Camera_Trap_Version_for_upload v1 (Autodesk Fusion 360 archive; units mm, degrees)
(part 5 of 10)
sketch "Sketch25" plane through (105, 0, 0) normal (-1, 0, 0) x axis (0, -1, 0)
  line L1 (-34.2232, 143.2913) -> (-36.1659, 143.2913)
  line L2 (-34.2, 143.2798) -> (-34.2232, 143.2913)
  line L3 (-36.1659, 143.2798) -> (-34.2, 143.2798)
  line L4 (-36.1659, 143.2913) -> (-36.1659, 143.2798)
  line L5 (-36.1659, 139.8364) -> (-36.1659, 139.8248)
  line L6 (-34.2, 139.8364) -> (-36.1659, 139.8364)
  line L7 (-34.2232, 139.8248) -> (-34.2, 139.8364)
  line L8 (-36.1659, 139.8248) -> (-34.2232, 139.8248)
  line L9 (10, 119) -> (-33, 119)
  line L10 (18, 145) -> (18, 127)
  line L11 (-33, 153) -> (10, 153)
  line L12 (-41, 127) -> (-41, 145)
  line L13 (11.3693, 148.5581) -> (-24.3276, 148.5581)
  line L14 (11.3693, 123.5581) -> (-24.3276, 123.5581)
  line L15 (-33.7807, 138.4085) -> (-33.7807, 138.4081)
  line L16 (-33.7807, 138.4085) -> (-34.161, 138.0281)
  line L17 (-34.161, 145.088) -> (-33.7807, 144.7077)
  line L18 (-33.7807, 144.7081) -> (-33.7807, 144.7077)
  line L19 (-36.1659, 143.2798) -> (-36.1659, 143.2913)
  line L20 (-36.1659, 143.2913) -> (-34.2232, 143.2913)
  line L21 (-34.2, 143.2798) -> (-34.2232, 143.2913)
  line L22 (-36.661, 145.088) -> (-34.161, 145.088)
  curve K1 (-37.1562, 143.1166) -> (-37.1489, 143.0744)
  line L23 (-36.1659, 143.2798) -> (-34.2, 143.2798)
  line L24 (-36.1659, 139.8364) -> (-34.2, 139.8364)
  curve K2 (-37.1562, 144.5928) -> (-36.661, 145.088)
  line L25 (-37.1562, 143.1187) -> (-37.1562, 143.1166)
  line L26 (-36.1659, 139.8248) -> (-36.1659, 139.8364)
  line L27 (-36.1659, 139.8248) -> (-34.2232, 139.8248)
  line L28 (-34.2232, 139.8248) -> (-34.2, 139.8364)
  line L29 (-36.661, 138.0281) -> (-34.161, 138.0281)
  curve K3 (-37.1562, 143.0321) -> (-37.1489, 143.0744)
  curve K4 (-37.1489, 140.0417) -> (-37.1562, 140.084)
  line L30 (-24.3276, 123.5581) -> (-32.6307, 123.5581)
  line L31 (-24.3276, 148.5581) -> (-32.6307, 148.5581)
  line L32 (-33.6307, 147.5581) -> (-33.6307, 144.5581)
  line L33 (-33.6307, 133.5581) -> (-33.6307, 138.5581)
  line L34 (-33.6307, 127.5581) -> (-33.6307, 124.5581)
  line L35 (12.3693, 127.5581) -> (12.3693, 144.5581)
  line L36 (12.3693, 147.5581) -> (12.3693, 144.5581)
  line L37 (12.3693, 127.5581) -> (12.3693, 124.5581)
  line L38 (-37.1562, 139.9995) -> (-37.1562, 139.9974)
  curve K5 (-36.661, 138.0281) -> (-37.1562, 138.5233)
  line L39 (-33.7807, 127.5581) -> (-33.7807, 128.0581)
  line L40 (-33.7807, 133.0581) -> (-33.7807, 133.5581)
  line L41 (-36.6307, 128.0581) -> (-36.6307, 130.5581)
  line L42 (-36.6307, 130.5581) -> (-36.6307, 133.0581)
  line L43 (-33.7807, 144.7081) -> (-33.6307, 144.5581)
  line L44 (-33.7807, 138.4081) -> (-33.6307, 138.5581)
  line L45 (-37.1562, 143.1187) -> (-37.1562, 144.5928)
  line L46 (-37.1562, 140.084) -> (-37.1562, 143.0321)
  line L47 (-37.1562, 138.5233) -> (-37.1562, 139.9974)
  line L48 (-33.6307, 127.5581) -> (-33.7807, 127.5581)
  line L49 (-33.6307, 133.5581) -> (-33.7807, 133.5581)
  line L50 (-33.7807, 128.0581) -> (-36.6307, 128.0581)
  line L51 (-33.7807, 133.0581) -> (-36.6307, 133.0581)
  line L52 (-46.5669, 127) -> (-46.5669, 145)
  line L53 (10, 113.4331) -> (-33, 113.4331)
  line L54 (23.5669, 145) -> (23.5669, 127)
  line L55 (-33, 158.5669) -> (10, 158.5669)
  arc A1 centre (-33, 127) radius 8 clockwise from (-33, 119) to (-41, 127)
  arc A2 centre (10, 127) radius 8 clockwise from (18, 127) to (10, 119)
  arc A3 centre (10, 145) radius 8 clockwise from (10, 153) to (18, 145)
  arc A4 centre (-33, 145) radius 8 clockwise from (-41, 145) to (-33, 153)
  closed curve K6 centre (-36.6611, 139.9995)
  arc A5 centre (11.3693, 124.5581) radius 1 clockwise from (12.3693, 124.5581) to (11.3693, 123.5581)
  arc A6 centre (11.3693, 147.5581) radius 1 clockwise from (11.3693, 148.5581) to (12.3693, 147.5581)
  arc A7 centre (-32.6307, 147.5581) radius 1 clockwise from (-33.6307, 147.5581) to (-32.6307, 148.5581)
  arc A8 centre (-32.6307, 124.5581) radius 1 clockwise from (-32.6307, 123.5581) to (-33.6307, 124.5581)
  arc A9 centre (-33, 145) radius 13.5669 clockwise from (-46.5669, 145) to (-33, 158.5669)
  arc A10 centre (-33, 127) radius 13.5669 clockwise from (-33, 113.4331) to (-46.5669, 127)
  arc A11 centre (10, 127) radius 13.5669 clockwise from (23.5669, 127) to (10, 113.4331)
  arc A12 centre (10, 145) radius 13.5669 clockwise from (10, 158.5669) to (23.5669, 145)
  dimension "d1087" = 5.5669
extrude "Extrude51" add sketch "Sketch25" profile of A1 L9 A2 L10 A3 L11 A4 L12 A12 A9 A10 A11 L55 L53 L54 L52 against normal blind 20
extrude "Extrude4" cut sketch "Sketch25" profile of L1 L2 L3 L4 L5 L6 L7 L8 A1 L9 A2 L10 A3 L11 A4 L12 L13 L14 L15 L16 L17 L18 L19 L20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 blind -24 from offset -3
sketch "Sketch26" plane through (0, 46.5669, 0) normal (0, 1, 0) x axis (-1, 0, 0)
  line L1 (-105, 145) -> (-105, 127)
  line L2 (-125, 145) -> (-105, 145)
  line L3 (-125, 127) -> (-125, 145)
  line L4 (-105, 127) -> (-125, 127)
  line L5 (-113, 135) -> (-125, 135)
  line L6 (-113, 127) -> (-113, 135)
  line L7 (-125, 127) -> (-113, 127)
  line L8 (-125, 135) -> (-125, 127)
  point P6 (-125, 135)
  point P7 (-113, 135)
  horizontal L5
  vertical L6
  horizontal L7
  vertical L8
  dimension "d1096" distance P6 P7 = 12
extrude "Extrude53" cut sketch "Sketch26" profile of L3 L4 L5 L6 L7 L8 against normal blind 10
sketch "Sketch27" plane through (132, 0, 0) normal (1, 0, 0) x axis (0, 1, 0)
  line L1 (-10, 119) -> (33, 119)
  line L2 (-18, 145) -> (-18, 127)
  line L3 (33, 153) -> (-10, 153)
  line L4 (41, 127) -> (41, 145)
  line L5 (53, 254.9308) -> (53, 30)
  line L6 (2.6295, 254.9308) -> (53, 254.9308)
  line L7 (-35.395, 253.2053) -> (-2.6295, 254.9308)
  curve K1 (-35.395, 253.2053) -> (-39.3474, 235.851)
  line L8 (33, 30) -> (2.8201, 30)
  line L9 (53, 30) -> (33, 30)
  line L10 (41, 136) -> (-18, 136)
  line L11 (11, 153) -> (11.5, 119)
  arc A1 centre (33, 127) radius 8 clockwise from (41, 127) to (33, 119)
  arc A2 centre (-10, 127) radius 8 clockwise from (-10, 119) to (-18, 127)
  arc A3 centre (-10, 145) radius 8 clockwise from (-18, 145) to (-10, 153)
  arc A4 centre (33, 145) radius 8 clockwise from (33, 153) to (41, 145)
  arc A5 centre (0, 205) radius 50 clockwise from (-2.6295, 254.9308) to (2.6295, 254.9308)
  arc A6 centre (0, 205) radius 50 clockwise from (-40.632, 175.8617) to (-39.3474, 235.851)
  arc A7 centre (-81.264, 146.7234) radius 50 clockwise from (-40.632, 175.8617) to (-31.815, 139.3208)
  arc A8 centre (-1.7685, 134.8228) radius 30.3814 clockwise from (-32.1399, 134.0465) to (-31.815, 139.3208)
  arc A9 centre (-82.1236, 132.769) radius 50 clockwise from (-32.1399, 134.0465) to (-39.6517, 106.3845)
  arc A10 centre (2.8201, 80) radius 50 clockwise from (2.8201, 30) to (-39.6517, 106.3845)
  circle C1 centre (-17.953, 152.353) radius 1.4
  circle C2 centre (39.9595, 153.2046) radius 1.4
  circle C3 centre (39.9595, 118.7954) radius 1.4
  circle C4 centre (-16.9412, 117.9586) radius 1.4
  point P32 (-18, 136)
  point P33 (41, 136)
  point P34 (11.5, 119)
  point P35 (11, 153)
  midpoint L2 P32
  midpoint L4 P33
  midpoint L1 P34
  coincident L3 P35
  symmetric C1 L11 C2
  symmetric L10 C2 C3
  symmetric L11 C3 C4
  dimension "d1099" diameter C1 = 2.8
extrude "Extrude54" cut sketch "Sketch27" profile of C1 C2 C3 C4 against normal blind 5
combine "Combine1" bodies "Right_wall (2)"
combine "Combine2"
sketch "Sketch3" plane through (136, 0, 0) normal (1, 0, 0) x axis (0, 1, 0)
  circle C1 centre (0, 70.6) radius 4.1
  circle C2 centre (0, 70.6) radius 25
  concentric C1 C2
  dimension "d1102" diameter C2 = 50
extrude "Extrude7" new body sketch "Sketch3" distance 10 bodies "wrong_cutting_tool"
thread "Thread1" ThreadOffset 0 ThreadLength 10
combine "Combine6" bodies "Right_wall (2) (1)"
extrude "Extrude55" cut of existing geometry blind -10
extrude "Extrude10" new body sketch "Sketch1" profile of C1 C2 C3 L1 L2 L3 L4 A1 A2 A3 A4 L7 C4 C5 C6 C7 C8 C9 C10 C11 along normal blind 8
combine "Combine7" bodies "Right_wall_Final"
extrude "Extrude5" cut of existing geometry blind -20
combine "Combine8"
extrude "Extrude11" cut of existing geometry blind -10
extrude "Extrude12" cut of existing geometry blind -15
extrude "Extrude13" cut of existing geometry blind -15
extrude "Extrude14" cut of existing geometry blind -15
extrude "Extrude61" new body sketch "Small_bearings_R" profile of C4 C5 C6 C7 C8 C9 C13 C14 against normal blind 12 bodies "Cut_tool"
extrude "Extrude62" new body sketch "Small_bearings_R" profile of C1 C2 C3 C10 C11 C12 C15 C16 against normal blind 12 bodies "Cut_tool (1)"
thread "Thread1" ThreadOffset 0 ThreadLength 10
thread "Thread2" ThreadOffset 0 ThreadLength 10
combine "Combine9"
extrude "Extrude63" new body sketch "Small_bearings_L" profile of C1 C2 C4 C5 C7 C8 along normal blind 4
extrude "Extrude64" add of existing geometry blind 4
extrude "Extrude65" cut of existing geometry blind -4
sketch "Sketch8" plane through (0, 0, 0) normal (1, 0, 0) x axis (0, 1, 0)
sketch "Sketch9" plane through (135.8025, 0, 0) normal (1, 0, 0) x axis (0, 1, 0)
  line L1 (52.3693, 253.4503) -> (59.3693, 253.4503)
  line L2 (52.3693, 30.245) -> (52.3693, 253.4503)
  line L3 (59.3693, 30.245) -> (52.3693, 30.245)
  line L4 (59.3693, 253.4503) -> (59.3693, 30.245)
  line L5 (64.8196, 255.1758) -> (59.3693, 249.9246)
  line L6 (64.8196, 265) -> (64.8196, 255.1758)
  line L7 (59.3693, 265) -> (64.8196, 265)
  line L8 (59.3693, 265) -> (59.3693, 253.4503)
  point P6 (59.3693, 249.9246)
  point P2 (59.3693, 253.4503)
  point P9 (59.3693, 253.4503)
  coincident L4 P6
  vertical L6
  perpendicular L6 L7
  coincident P2 P9
  perpendicular L7 L8
sweep "Sweep1" sketch "Sketch9" TwistAngle 0 TaperAngle 0
combine "Combine1" bodies "BackWall"
combine "Combine1" sketch "Tests" bodies "Right_wall_Final"
combine "Combine1" bodies "Right_wall_Final"
combine "Combine1" bodies "Right_wall_Final"
combine "Combine1" sketch "Tests" bodies "Print_Test"
combine "Combine1" bodies "interior_motor_holder"
component_from_bodies "Body->Comp1"
offset_faces "OffsetFaces1" distance -1
offset_faces "OffsetFaces2" distance -1
offset_faces "OffsetFaces1" distance 1
offset_faces "OffsetFaces2" distance 1
sketch "Sketch1" plane through (0, 35, 0) normal (0, -1, 0) x axis (1, 0, 0)
  line L1 (61.25, 114.9665) -> (61.25, 151.0335)
  line L2 (51.25, 114.9665) -> (61.25, 114.9665)
  line L3 (51.25, 151.0335) -> (51.25, 114.9665)
  line L4 (61.25, 151.0335) -> (51.25, 151.0335)
  line L5 (-7.775, 205) -> (-7.775, 207.6585)
  line L6 (-21, 205) -> (-7.775, 205)
  line L7 (-21, 195.1585) -> (-21, 205)
  line L8 (-7.775, 195.1585) -> (-21, 195.1585)
  line L9 (-7.775, 175.1585) -> (-7.775, 195.1585)
  line L10 (33.225, 170.1585) -> (-2.775, 170.1585)
  line L11 (43.225, 110.9415) -> (43.225, 160.1585)
  line L12 (64.275, 105.9415) -> (48.225, 105.9415)
  line L13 (69.275, 175.1585) -> (69.275, 110.9415)
  line L14 (12.225, 180.1585) -> (64.275, 180.1585)
  line L15 (2.225, 208.1585) -> (2.225, 190.1585)
  line L16 (-5.275, 210.1585) -> (0.225, 210.1585)
  line L17 (48.7344, 135.5025) -> (48.7344, 145.5025)
  line L18 (45.7344, 145.5025) -> (45.7344, 135.5025)
  line L19 (66.7656, 135.5025) -> (66.7656, 145.5025)
  line L20 (63.7656, 145.5025) -> (63.7656, 135.5025)
  line L21 (65.2656, 146.5025) -> (65.2656, 145.5025)
  line L22 (63.7656, 146.5025) -> (63.7656, 145.5025)
  line L23 (66.7656, 146.5025) -> (66.7656, 145.5025)
  line L24 (65.5, 140.5025) -> (66.7656, 140.5025)
  line L25 (65.5, 140.5025) -> (66.7656, 140.5025)
  line L26 (66.7656, 134.5025) -> (66.7656, 135.5025)
  line L27 (63.7656, 134.5025) -> (63.7656, 135.5025)
  line L28 (56.25, 147) -> (56.25, 151.0335)
  line L29 (45.7344, 146.5025) -> (45.7344, 145.5025)
  line L30 (48.7344, 146.5025) -> (48.7344, 145.5025)
  line L31 (48.7344, 145.5025) -> (48.7344, 135.5025)
  line L32 (45.7344, 135.5025) -> (45.7344, 145.5025)
  line L33 (45.7344, 134.5025) -> (45.7344, 135.5025)
  line L34 (48.7344, 134.5025) -> (48.7344, 135.5025)
  line L35 (43.225, 119.0366) -> (3.126, 170.1585)
  line L36 (43.225, 132.2223) -> (13.4686, 170.1585)
  arc A1 centre (-5.275, 207.6585) radius 2.5 clockwise from (-7.775, 207.6585) to (-5.275, 210.1585)
  arc A2 centre (-2.775, 175.1585) radius 5 clockwise from (-2.775, 170.1585) to (-7.775, 175.1585)
  arc A3 centre (33.225, 160.1585) radius 10 clockwise from (33.225, 170.1585) to (43.225, 160.1585)
  arc A4 centre (48.225, 110.9415) radius 5 clockwise from (48.225, 105.9415) to (43.225, 110.9415)
  arc A5 centre (64.275, 110.9415) radius 5 clockwise from (69.275, 110.9415) to (64.275, 105.9415)
  arc A6 centre (64.275, 175.1585) radius 5 clockwise from (64.275, 180.1585) to (69.275, 175.1585)
  arc A7 centre (12.225, 190.1585) radius 10 clockwise from (12.225, 180.1585) to (2.225, 190.1585)
  arc A8 centre (0.225, 208.1585) radius 2 clockwise from (0.225, 210.1585) to (2.225, 208.1585)
  arc A9 centre (47.2344, 135.5025) radius 1.5 clockwise from (48.7344, 135.5025) to (45.7344, 135.5025)
  arc A10 centre (47.2344, 145.5025) radius 1.5 clockwise from (45.7344, 145.5025) to (48.7344, 145.5025)
  arc A11 centre (65.2656, 135.5025) radius 1.5 clockwise from (66.7656, 135.5025) to (63.7656, 135.5025)
  arc A12 centre (65.2656, 145.5025) radius 1.5 clockwise from (63.7656, 145.5025) to (66.7656, 145.5025)
  circle C1 centre (65.2656, 145.5025) radius 1.5
  circle C2 centre (65.2656, 146.5025) radius 1.5
  circle C3 centre (65.2656, 134.5025) radius 1.5
  circle C4 centre (47.2344, 146.5025) radius 1.5
  circle C5 centre (47.2344, 134.5025) radius 1.5
  point P40 (66.7656, 145.5025)
  point P46 (65.2656, 145.5025)
  point P47 (65.2656, 145.5025)
  point P48 (65.2656, 146.5025)
  point P49 (65.2656, 146.5025)
  point P44 (63.7656, 145.5025)
  point P50 (63.7656, 145.5025)
  point P51 (63.7656, 146.5025)
  point P52 (66.7656, 145.5025)
  point P53 (66.7656, 146.5025)
  point P54 (66.7656, 140.5025)
  point P61 (63.7656, 135.5025)
  point P62 (63.7656, 134.5025)
  point P59 (66.7656, 135.5025)
  point P60 (66.7656, 134.5025)
  point P56 (66.7656, 140.5025)
  point P55 (65.5, 140.5025)
  point P57 (65.5, 140.5025)
  point P63 (56.25, 151.0335)
  point P72 (45.7344, 145.5025)
  point P41 (66.7656, 135.5025)
  point P73 (45.7344, 135.5025)
  point P42 (63.7656, 135.5025)
  point P70 (48.7344, 135.5025)
  point P71 (48.7344, 145.5025)
  point P68 (48.7344, 145.5025)
  point P69 (48.7344, 146.5025)
  point P66 (45.7344, 145.5025)
  point P67 (45.7344, 146.5025)
  point P74 (45.7344, 135.5025)
  point P75 (45.7344, 134.5025)
  point P76 (48.7344, 135.5025)
  point P77 (48.7344, 134.5025)
  point P79 (3.126, 170.1585)
  point P80 (43.225, 119.0366)
  point P81 (13.4686, 170.1585)
  point P82 (43.225, 132.2223)
  concentric A12 C1
  coincident P40 C1
  coincident P46 P47
  vertical L21
  coincident P48 P49
  coincident P44 P50
  coincident C2 P51
  tangent C2 L22
  coincident P40 P52
  coincident C2 P53
  tangent C2 L23
  midpoint L19 P54
  perpendicular L19 L24
  symmetric C2 L24 C3
  symmetric P50 L24 P61
  symmetric P51 L24 P62
  symmetric P52 L24 P59
  symmetric P53 L24 P60
  symmetric P54 L24 P56
  symmetric P55 L24 P57
  midpoint L4 P63
  perpendicular L4 L28
  symmetric P40 L28 P72
  symmetric P41 L28 P73
  symmetric P42 L28 P70
  symmetric P44 L28 P71
  symmetric C2 L28 C4
  symmetric P50 L28 P68
  symmetric P51 L28 P69
  symmetric P52 L28 P66
  symmetric P53 L28 P67
  symmetric C3 L28 C5
  symmetric P59 L28 P74
  symmetric P60 L28 P75
  symmetric P61 L28 P76
  symmetric P62 L28 P77
  coincident L10 P79
  coincident L11 P80
  coincident L10 P81
  coincident L11 P82
  parallel L35 L36
  dimension "d1241" distance P47 P48 = 1
  dimension "d1242" diameter C2 = 3
extrude "Extrude1" cut sketch "Sketch1" profile of A9 A10 A11 A12 C1 C2 L22 L23 C3 L26 L27 C4 L29 L30 L33 L34 C5 to an object
offset_faces "OffsetFaces3" distance -0.1
offset_faces "OffsetFaces4" distance -0.1
offset_faces "OffsetFaces5" distance -0.1
offset_faces "OffsetFaces6" distance -0.1
extrude "Extrude2" add sketch "Sketch1" profile of L10 L11 L35 L36 against normal blind 6
offset_faces "OffsetFaces7" distance -1
scale "Scale1" ScaleFactor 0.97
copy_paste_bodies "CopyPasteBodies3"
base_feature "Base Feature1" bodies "Right_Wall_Cap_Low (1)", "Handle_Exterior"
sketch "Sketch1" plane through (0, 0, 0) normal (0, 1, 0) x axis (1, 0, 0)
  line L1 (129, -220.4) -> (129, -190.4)
  line L2 (129, -190.4) -> (129, -180.4)
  line L3 (129, -180.4) -> (136, -180.4)
  line L4 (129, -230.4) -> (136, -230.4)
  line L5 (129, -230.4) -> (129, -220.4)
  line L6 (136, -230.4) -> (136, -235.4)
  line L7 (136, -175.4) -> (136, -180.4)
  line L8 (139, -235.4) -> (136, -235.4)
  line L9 (139, -175.4) -> (136, -175.4)
  line L10 (139, -175.4) -> (139, -190.4)
  line L11 (139, -190.4) -> (139, -220.4)
  line L12 (139, -220.4) -> (139, -235.4)
  line L13 (158, -168.5) -> (158, -196)
  line L14 (158, -196) -> (158, -223.5)
  line L15 (138, -168.5) -> (138, -182.9)
  line L16 (138, -209.1) -> (138, -223.5)
  line L17 (129, -182.9) -> (129, -196)
  line L18 (129, -196) -> (129, -209.1)
  line L19 (158, -223.5) -> (138, -223.5)
  line L20 (158, -168.5) -> (138, -168.5)
  line L21 (138, -209.1) -> (129, -209.1)
  line L22 (138, -182.9) -> (129, -182.9)
extrude "Extrude2" new body of existing geometry blind 9 named "d703_1" bodies "Coil"
thread "Thread1" ThreadOffset 0 named "d705_1" ThreadLength 10 named "d706_1"
fillet "Fillet1" radius 5 named "d708_1"
scale "Scale1" ScaleFactor 0.97 named "d1151_1"
combine "Combine1" bodies "Right_wall_Final"
sketch "Sketch6" plane through (135.8025, 0, 0) normal (1, 0, 0) x axis (0, 1, 0)
  curve K1 (-42.0969, 92.8551) -> (-42.4569, 81.9281)
  curve K2 (-35.7603, 81.9281) -> (-36.1203, 92.8551)
  curve K3 (-42.0969, 202.8551) -> (-42.4569, 191.9281)
  curve K4 (-35.7603, 191.9281) -> (-36.1203, 202.8551)
  line L1 (1.9988, 255.1758) -> (52.3693, 255.1758)
  line L2 (-36.0257, 253.4503) -> (-3.2602, 255.1758)
  curve K5 (-36.0257, 253.4503) -> (-39.9781, 236.096)
  line L3 (32.3693, 30.245) -> (2.1894, 30.245)
  line L4 (52.3693, 30.245) -> (32.3693, 30.245)
  line L5 (59.3693, 30.245) -> (52.3693, 30.245)
  line L6 (59.3693, 249.9246) -> (59.3693, 30.245)
  line L7 (64.8196, 255.1758) -> (59.3693, 249.9246)
  line L8 (64.8196, 265) -> (64.8196, 255.1758)
  line L9 (59.3693, 265) -> (64.8196, 265)
  line L10 (59.3693, 253.4503) -> (59.3693, 265)
  line L11 (-10.6307, 119.245) -> (32.3693, 119.245)
  line L12 (-18.6307, 145.245) -> (-18.6307, 127.245)
  line L13 (32.3693, 153.245) -> (-10.6307, 153.245)
  line L14 (40.3693, 127.245) -> (40.3693, 145.245)
  curve K6 (3.3853, 45.9804) -> (18.082, 84.0954)
  curve K7 (-6.8655, 92.093) -> (-17.0683, 52.5374)
  line L15 (-25, 220.4) -> (-25, 190.4)
  line L16 (15, 230.4) -> (-15, 230.4)
  line L17 (25, 190.4) -> (25, 220.4)
  line L18 (-15, 180.4) -> (15, 180.4)
  line L19 (-60.3135, 107.7788) -> (-50, 270)
  line L20 (33.9876, 93.3188) -> (-60.3135, 107.7788)
  line L21 (20.222, 41.7577) -> (33.9876, 93.3188)
  line L22 (-41.5097, 45.9804) -> (20.222, 41.7577)
  line L23 (-12.1668, 16.3902) -> (-41.5097, 45.9804)
  line L24 (70, 20) -> (-12.1668, 16.3902)
  line L25 (70, 273.158) -> (70, 20)
  line L26 (-50, 270) -> (70, 273.158)
  line L27 (-41.5097, 45.9804) -> (-47.6821, 105.8419)
  line L28 (52.3693, 255.1758) -> (52.3693, 253.4503)
  line L29 (52.3693, 253.4503) -> (59.3693, 253.4503)
  arc A1 centre (-39.1086, 86.6236) radius 6.911 clockwise from (-42.0969, 92.8551) to (-36.1203, 92.8551)
  arc A2 centre (-39.1086, 86.6236) radius 5.767 clockwise from (-35.7603, 81.9281) to (-42.4569, 81.9281)
  arc A3 centre (-39.1086, 196.6236) radius 6.911 clockwise from (-42.0969, 202.8551) to (-36.1203, 202.8551)
  arc A4 centre (-39.1086, 196.6236) radius 5.767 clockwise from (-35.7603, 191.9281) to (-42.4569, 191.9281)
  circle C1 centre (27.5, 205.4) radius 1.65
  circle C2 centre (0, 177.9) radius 1.65
  circle C3 centre (-27.5, 205.4) radius 1.65
  circle C4 centre (0, 232.9) radius 1.65
  arc A5 centre (-0.6307, 205.245) radius 50 clockwise from (-3.2602, 255.1758) to (1.9988, 255.1758)
  arc A6 centre (-0.6307, 205.245) radius 50 clockwise from (-41.2627, 176.1067) to (-39.9781, 236.096)
  arc A7 centre (-81.8947, 146.9684) radius 50 clockwise from (-41.2627, 176.1067) to (-32.4457, 139.5658)
  arc A8 centre (-2.3992, 135.0677) radius 30.3814 clockwise from (-32.7706, 134.2915) to (-32.4457, 139.5658)
  arc A9 centre (-82.7543, 133.0139) radius 50 clockwise from (-32.7706, 134.2915) to (-40.2825, 106.6295)
  arc A10 centre (2.1894, 80.245) radius 50 clockwise from (2.1894, 30.245) to (-40.2825, 106.6295)
  arc A11 centre (32.3693, 127.245) radius 8 clockwise from (40.3693, 127.245) to (32.3693, 119.245)
  arc A12 centre (-10.6307, 127.245) radius 8 clockwise from (-10.6307, 119.245) to (-18.6307, 127.245)
  arc A13 centre (-10.6307, 145.245) radius 8 clockwise from (-18.6307, 145.245) to (-10.6307, 153.245)
  arc A14 centre (32.3693, 145.245) radius 8 clockwise from (32.3693, 153.245) to (40.3693, 145.245)
  circle C5 centre (39.3288, 119.0404) radius 1.4
  circle C6 centre (39.3288, 153.4496) radius 1.4
  circle C7 centre (-17.5719, 118.2036) radius 1.4
  circle C8 centre (-18.5837, 152.598) radius 1.4
  arc A15 centre (0, 70.6) radius 24.8513 clockwise from (3.3853, 45.9804) to (-17.0683, 52.5374)
  arc A16 centre (0, 70.6) radius 22.5629 clockwise from (-6.8655, 92.093) to (18.082, 84.0954)
  arc A17 centre (-15, 220.4) radius 10 clockwise from (-25, 220.4) to (-15, 230.4)
  arc A18 centre (15, 220.4) radius 10 clockwise from (15, 230.4) to (25, 220.4)
  arc A19 centre (15, 190.4) radius 10 clockwise from (25, 190.4) to (15, 180.4)
  arc A20 centre (-15, 190.4) radius 10 clockwise from (-15, 180.4) to (-25, 190.4)
  point P79 (-47.6821, 105.8419)
  parallel L8 L25
  coincident L20 P79
extrude "Extrude1" cut sketch "Sketch6" profile of K3 A3 K4 A4 C1 C2 C3 C4 L1 A5 L2 K5 A6 A7 A8 A9 A10 L3 L4 L5 L6 L7 L8 L9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 against normal blind 240 bodies "Right_wall_Final (1)"
combine "Combine1"
offset_faces "OffsetFaces1" distance 7
position "Position29"
sketch "Sketch28" plane through (-24, 0, 0) normal (-1, 0, 0) x axis (0, -1, 0)
  line L1 (-46.1387, 104.755) -> (-18.6307, 104.755)
  line L2 (-49.1387, 175.7967) -> (-49.1387, 107.755)
  line L3 (-18.6307, 178.7967) -> (-46.1387, 178.7967)
  line L4 (-15.6307, 107.755) -> (-15.6307, 175.7967)
  line L5 (-35, 194) -> (-35, 213)
  line L6 (-42, 194) -> (-35, 194)
  line L7 (-42, 213) -> (-42, 194)
  line L8 (-35, 213) -> (-42, 213)
  line L9 (-53, 30) -> (-53, 254.9308)
  line L10 (-33, 30) -> (-53, 30)
  line L11 (-2.8201, 30) -> (-33, 30)
  curve K1 (35.395, 253.2053) -> (39.3474, 235.851)
  line L12 (2.6295, 254.9308) -> (35.395, 253.2053)
  line L13 (-53, 254.9308) -> (-2.6295, 254.9308)
  line L14 (2.6295, 254.9308) -> (35.395, 253.2053)
  curve K2 (35.395, 253.2053) -> (39.3474, 235.851)
  line L15 (-53, 30) -> (-53, 254.9308)
  line L16 (-53, 253.2053) -> (35.395, 253.2053)
  line L17 (-2.6295, 254.9308) -> (-60, 254.9308)
  arc A1 centre (-46.1387, 107.755) radius 3 clockwise from (-46.1387, 104.755) to (-49.1387, 107.755)
  arc A2 centre (-46.1387, 175.7967) radius 3 clockwise from (-49.1387, 175.7967) to (-46.1387, 178.7967)
  arc A3 centre (-18.6307, 175.7967) radius 3 clockwise from (-18.6307, 178.7967) to (-15.6307, 175.7967)
  arc A4 centre (-18.6307, 107.755) radius 3 clockwise from (-15.6307, 107.755) to (-18.6307, 104.755)
  arc A5 centre (-2.8201, 80) radius 50 clockwise from (39.6517, 106.3845) to (-2.8201, 30)
  arc A6 centre (82.1236, 132.769) radius 50 clockwise from (39.6517, 106.3845) to (32.1399, 134.0465)
  arc A7 centre (1.7685, 134.8228) radius 30.3814 clockwise from (31.815, 139.3208) to (32.1399, 134.0465)
  arc A8 centre (81.264, 146.7234) radius 50 clockwise from (31.815, 139.3208) to (40.632, 175.8617)
  arc A9 centre (0, 205) radius 50 clockwise from (39.3474, 235.851) to (40.632, 175.8617)
  arc A10 centre (0, 205) radius 50 clockwise from (-2.6295, 254.9308) to (2.6295, 254.9308)
  arc A11 centre (0, 205) radius 50 clockwise from (-2.6295, 254.9308) to (2.6295, 254.9308)
  point P35 (35.395, 253.2053)
  point P40 (35.395, 253.2053)
  point P41 (-53, 253.2053)
  coincident P35 P40
  coincident L9 P41
  perpendicular L9 L16
extrude "Extrude66" cut sketch "Sketch28" profile of L9 L12 A10 L13 L14 L15 L16 L17 A11 to an object
sketch "Sketch1" plane through (135.8025, 0, 0) normal (1, 0, 0) x axis (0, 1, 0)
  curve K1 (3.2949, 46.7854) -> (18.5796, 87.8321)
  curve K2 (-2.3861, 97.1189) -> (-22.5143, 58.2176)
  line L1 (-10.6307, 119.245) -> (32.3693, 119.245)
  line L2 (-18.6307, 145.245) -> (-18.6307, 127.245)
  line L3 (32.3693, 153.245) -> (-10.6307, 153.245)
  line L4 (40.3693, 127.245) -> (40.3693, 145.245)
  line L5 (52.3693, 255.1758) -> (52.3693, 30.245)
  line L6 (1.9988, 255.1758) -> (52.3693, 255.1758)
  line L7 (-36.0257, 253.4503) -> (-3.2602, 255.1758)
  curve K3 (-36.0257, 253.4503) -> (-39.9781, 236.096)
  line L8 (32.3693, 30.245) -> (2.1894, 30.245)
  line L9 (52.3693, 30.245) -> (32.3693, 30.245)
  line L10 (52.3693, 30.245) -> (52.3693, 255.1758)
  line L11 (1.9988, 255.1758) -> (52.3693, 255.1758)
  line L12 (52.3693, 253.4503) -> (-36.0257, 253.4503)
  arc A1 centre (-1.593, 70.6) radius 24.311 clockwise from (3.2949, 46.7854) to (-22.5143, 58.2176)
  arc A2 centre (-1.593, 70.6) radius 26.5307 clockwise from (-2.3861, 97.1189) to (18.5796, 87.8321)
  circle C1 centre (-18.5837, 152.598) radius 1.4
  circle C2 centre (-17.5719, 118.2036) radius 1.4
  circle C3 centre (39.3288, 153.4496) radius 1.4
  circle C4 centre (39.3288, 119.0404) radius 1.4
  arc A3 centre (32.3693, 127.245) radius 8 clockwise from (40.3693, 127.245) to (32.3693, 119.245)
  arc A4 centre (-10.6307, 127.245) radius 8 clockwise from (-10.6307, 119.245) to (-18.6307, 127.245)
  arc A5 centre (-10.6307, 145.245) radius 8 clockwise from (-18.6307, 145.245) to (-10.6307, 153.245)
  arc A6 centre (32.3693, 145.245) radius 8 clockwise from (32.3693, 153.245) to (40.3693, 145.245)
  arc A7 centre (-0.6307, 205.245) radius 50 clockwise from (-3.2602, 255.1758) to (1.9988, 255.1758)
  arc A8 centre (-0.6307, 205.245) radius 50 clockwise from (-41.2627, 176.1067) to (-39.9781, 236.096)
  arc A9 centre (-81.8947, 146.9684) radius 50 clockwise from (-41.2627, 176.1067) to (-32.4457, 139.5658)
  arc A10 centre (-2.3992, 135.0677) radius 30.3814 clockwise from (-32.7706, 134.2915) to (-32.4457, 139.5658)
  arc A11 centre (-82.7543, 133.0139) radius 50 clockwise from (-32.7706, 134.2915) to (-40.2825, 106.6295)
  arc A12 centre (2.1894, 80.245) radius 50 clockwise from (2.1894, 30.245) to (-40.2825, 106.6295)
  arc A13 centre (-0.6307, 205.245) radius 50 clockwise from (-3.2602, 255.1758) to (1.9988, 255.1758)
  point P28 (-36.0257, 253.4503)
  point P45 (-36.0257, 253.4503)
  point P46 (52.3693, 253.4503)
  coincident P28 P45
  coincident L10 P46
  perpendicular L10 L12
extrude "Extrude1" cut sketch "Sketch1" profile of L5 L6 A7 L7 L10 L11 A13 L12 to an object
sketch "right roof" plane through (132, 0, 0) normal (1, 0, 0) x axis (0, 1, 0)
  line L1 (-150.5352, 231.8021) -> (-151.5254, 235.0563)
  line L2 (-72.4247, 251.2552) -> (-148.3404, 230.5893)
  line L3 (-2.6295, 254.9308) -> (-72.4247, 251.2552)
  line L4 (60, 254.9308) -> (2.6295, 254.9308)
  line L5 (60, 294.5588) -> (60, 254.9308)
  line L6 (-150.2762, 237.3171) -> (60, 294.5588)
  line L7 (60, 287.304) -> (-72.4247, 251.2552)
  line L8 (53, 253.2053) -> (60, 253.2053)
  line L9 (53, 30) -> (53, 253.2053)
  line L10 (60, 30) -> (53, 30)
  line L11 (60, 253.2053) -> (60, 30)
  line L12 (53, 285.3985) -> (53, 253.2053)
  line L13 (-35.395, 253.2053) -> (53, 253.2053)
  line L14 (-65.2611, 253.2053) -> (53, 253.2053)
  circle C1 centre (6.6916, 266.9657) radius 3.15
  arc A1 centre (-149.8034, 235.5803) radius 1.8 clockwise from (-151.5254, 235.0563) to (-150.2762, 237.3171)
  arc A2 centre (-148.8131, 232.3261) radius 1.8 clockwise from (-148.3404, 230.5893) to (-150.5352, 231.8021)
  arc A3 centre (0, 205) radius 50 clockwise from (-2.6295, 254.9308) to (2.6295, 254.9308)
  point P9 (-72.4247, 251.2552)
  point P15 (-72.4247, 251.2552)
  point P16 (60, 287.304)
  point P18 (53, 253.2053)
  point P21 (53, 253.2053)
  point P22 (53, 285.3985)
  point P23 (53, 253.2053)
  point P25 (53, 253.2053)
  point P26 (-65.2611, 253.2053)
  coincident P9 P15
  coincident L5 P16
  parallel L6 L7
  coincident P18 P21
  coincident L7 P22
  parallel L5 L12
  coincident P23 P25
  coincident L7 P26
  parallel L13 L14
extrude "Extrude67" cut sketch "right roof" profile of L3 L7 L14 to an object
extrude "Extrude68" new body sketch "right roof" profile of L3 A3 L4 L9 L13 L14 to an object bodies "Roof"
extrude "Extrude69" cut sketch "right roof" profile of C1 L3 A3 L4 L7 L9 L12 L13 L14 to an object from offset -7
extrude "Extrude70" sketch "right roof" profile of L3 A3 L4 L9 L13 L14 to an object
combine "Combine10"
fillet "Fillet8" radius 2
combine "Combine11" bodies "Roof"
offset_faces "OffsetFaces2" distance 1.726
sketch "Sketch30" plane through (-24, 0, 0) normal (-1, 0, 0) x axis (0, -1, 0)
  line L1 (-60, 253.2048) -> (-60, 291.9415)
  line L2 (-53, 253.2053) -> (-53, 253.2048)
  line L3 (65.2611, 253.2053) -> (-53, 253.2053)
  line L4 (148.3404, 230.5893) -> (65.2611, 253.2053)
  line L5 (151.5254, 235.0563) -> (150.5352, 231.8021)
  line L6 (-57.4747, 293.8713) -> (150.2762, 237.3171)
  line L7 (-53, 253.2053) -> (35.395, 253.2053)
  line L8 (-53, 30) -> (-53, 253.2053)
  line L9 (-33, 30) -> (-53, 30)
  line L10 (-2.8201, 30) -> (-33, 30)
  curve K1 (35.395, 253.2053) -> (39.3474, 235.851)
  line L11 (-35, 194) -> (-35, 213)
  line L12 (-42, 194) -> (-35, 194)
  line L13 (-42, 213) -> (-42, 194)
  line L14 (-35, 213) -> (-42, 213)
  line L15 (-46.1387, 104.755) -> (-18.6307, 104.755)
  line L16 (-49.1387, 175.7967) -> (-49.1387, 107.755)
  line L17 (-18.6307, 178.7967) -> (-46.1387, 178.7967)
  line L18 (-15.6307, 107.755) -> (-15.6307, 175.7967)
  line L19 (-60, 30) -> (-60, 253.2053)
  line L20 (-53, 30) -> (-60, 30)
  line L21 (-53, 253.2053) -> (-53, 30)
  line L22 (-60, 248.2053) -> (-60, 253.2053)
  line L23 (34.4188, 248.2053) -> (-60, 248.2053)
  curve K2 (38, 257) -> (35.395, 253.2053)
  curve K3 (38, 257.3) -> (38, 257)
  curve K4 (37.95, 257.3) -> (38.05, 257.3)
  line L24 (-60, 257.3) -> (38, 257.3)
  line L25 (-61, 248.2053) -> (-60, 248.2053)
  line L26 (-61, 257.3) -> (-61, 248.2053)
  line L27 (-60, 257.3) -> (-61, 257.3)
  line L28 (-60, 248.2053) -> (-60, 257.3)
  arc A1 centre (-58, 291.9415) radius 2 clockwise from (-60, 291.9415) to (-57.4747, 293.8713)
  arc A2 centre (148.8131, 232.3261) radius 1.8 clockwise from (150.5352, 231.8021) to (148.3404, 230.5893)
  arc A3 centre (149.8034, 235.5803) radius 1.8 clockwise from (150.2762, 237.3171) to (151.5254, 235.0563)
  arc A4 centre (-2.8201, 80) radius 50 clockwise from (39.6517, 106.3845) to (-2.8201, 30)
  arc A5 centre (82.1236, 132.769) radius 50 clockwise from (39.6517, 106.3845) to (32.1399, 134.0465)
  arc A6 centre (1.7685, 134.8228) radius 30.3814 clockwise from (31.815, 139.3208) to (32.1399, 134.0465)
  arc A7 centre (81.264, 146.7234) radius 50 clockwise from (31.815, 139.3208) to (40.632, 175.8617)
  arc A8 centre (0, 205) radius 50 clockwise from (39.3474, 235.851) to (40.632, 175.8617)
  arc A9 centre (-46.1387, 107.755) radius 3 clockwise from (-46.1387, 104.755) to (-49.1387, 107.755)
  arc A10 centre (-46.1387, 175.7967) radius 3 clockwise from (-49.1387, 175.7967) to (-46.1387, 178.7967)
  arc A11 centre (-18.6307, 175.7967) radius 3 clockwise from (-18.6307, 178.7967) to (-15.6307, 175.7967)
  arc A12 centre (-18.6307, 107.755) radius 3 clockwise from (-15.6307, 107.755) to (-18.6307, 104.755)
  point P47 (-60, 253.2053)
  point P50 (-60, 253.2053)
  point P52 (34.4188, 248.2053)
  point P15 (35.395, 253.2053)
  point P53 (35.395, 253.2053)
  point P57 (38, 257.3)
  point P60 (-60, 257.3)
  point P51 (-60, 248.2053)
  point P61 (-61, 248.2053)
  coincident P47 P50
  coincident K1 P52
  perpendicular L19 L23
  coincident P15 P53
  midpoint P57 K4
  coincident L1 P60
  perpendicular L1 L24
  horizontal L25
  vertical L26
  horizontal L27
  vertical L28
  dimension "d1184" distance P50 P51 = 5
  dimension "d1185" distance P51 P61 = 1
extrude "Extrude71" new body sketch "Sketch30" profile of L1 L2 L3 L7 L8 K1 L19 L21 L22 L23 K2 K3 L24 L25 L26 L27 L28 along normal blind 1
extrude "Extrude72" sketch "Sketch30" profile of L1 L2 L3 L7 L8 K1 L19 L21 L22 L23 K2 K3 L24 L28 blind -1
extrude "Extrude73" sketch "Sketch30" profile of L1 L19 L22 L25 L26 L27 L28 to an object
combine "Combine12" bodies "Roof"
combine "Combine13"
fillet "Fillet9" radius 1
fillet "Fillet10" radius 2
sketch "Sketch31" plane through (0, 53, 0) normal (0, -1, 0) x axis (1, 0, 0)
  line L1 (132, 253.2048) -> (-24, 253.2048)
  line L2 (132, 253.2053) -> (132, 253.2048)
  line L3 (125, 253.2053) -> (132, 253.2053)
  line L4 (125, 285.3985) -> (125, 253.2053)
  line L5 (-17, 285.3985) -> (125, 285.3985)
  line L6 (-17, 253.2053) -> (-17, 285.3985)
  line L7 (-24, 253.2053) -> (-17, 253.2053)
  line L8 (-24, 253.2048) -> (-24, 253.2053)
  line L9 (97.3814, 253.2048) -> (77.3814, 253.2048)
  line L10 (97.3814, 285.3985) -> (97.3814, 253.2048)
  line L11 (77.3814, 285.3985) -> (97.3814, 285.3985)
  line L12 (77.3814, 253.2048) -> (77.3814, 285.3985)
  line L13 (120.7311, 259.5518) -> (97.3814, 259.5518)
  line L14 (120.7311, 253.2048) -> (120.7311, 259.5518)
  line L15 (97.3814, 253.2048) -> (120.7311, 253.2048)
  line L16 (97.3814, 259.5518) -> (97.3814, 253.2048)
  point P12 (97.3814, 285.3985)
  point P10 (77.3814, 253.2048)
  point P16 (120.7311, 253.2048)
  point P14 (97.3814, 259.5518)
  point P11 (97.3814, 253.2048)
  horizontal L9
  vertical L10
  horizontal L11
  vertical L12
  coincident L5 P12
  coincident L1 P10
  horizontal L13
  vertical L14
  horizontal L15
  vertical L16
  coincident L1 P16
  coincident L10 P14
  dimension "d1198" distance P10 P11 = 20
extrude "Extrude74" new body sketch "Sketch31" profile of L1 L5 L9 L10 L11 L12 L13 L14 L15 L16 against normal blind 5
combine "Combine14"
sketch "Sketch32" plane through (0, -68.6749, 252.2759) normal (0, 0.2627, -0.9649) x axis (-1, 0, 0)
  line L1 (-130, -82.5645) -> (-130, 3.5381)
  line L2 (22, -82.5645) -> (-130, -82.5645)
  line L3 (22, 3.5381) -> (22, -82.5645)
  line L4 (17, 3.5381) -> (22, 3.5381)
  line L5 (17, 126.1027) -> (17, 3.5381)
  line L6 (-77.3814, 126.1027) -> (17, 126.1027)
  line L7 (-97.3814, 126.1027) -> (-77.3814, 126.1027)
  line L8 (-125, 126.1027) -> (-97.3814, 126.1027)
  line L9 (-125, 3.5381) -> (-125, 126.1027)
  line L10 (-130, 3.5381) -> (-125, 3.5381)
  line L11 (-77.3814, 126.1027) -> (-97.3814, 126.1027)
  line L12 (-109.3548, -52.5645) -> (-109.3548, -82.5645)
  line L13 (-97.3814, 126.1027) -> (-77.3814, 126.1027)
  line L14 (-97.3814, -63.8973) -> (-97.3814, 126.1027)
  line L15 (-77.3814, -63.8973) -> (-97.3814, -63.8973)
  line L16 (-77.3814, 126.1027) -> (-77.3814, -63.8973)
  line L17 (-54, -52.5645) -> (-54, -82.5645)
  line L18 (-74, -2.5645) -> (-34, -2.5645)
  line L19 (-74, -102.5645) -> (-74, -2.5645)
  line L20 (-34, -102.5645) -> (-74, -102.5645)
  line L21 (-34, -2.5645) -> (-34, -102.5645)
  line L22 (-74, -102.5645) -> (-34, -2.5645)
  line L23 (-34, -102.5645) -> (-74, -2.5645)
  line L24 (-71.5, -2.5645) -> (-74, -2.5645)
  line L25 (-71.5, -47.5645) -> (-71.5, -2.5645)
  line L26 (-74, -47.5645) -> (-71.5, -47.5645)
  line L27 (-74, -2.5645) -> (-74, -47.5645)
  line L28 (-36.5, -2.5645) -> (-34, -2.5645)
  line L29 (-36.5, -47.5645) -> (-36.5, -2.5645)
  line L30 (-34, -47.5645) -> (-36.5, -47.5645)
  line L31 (-34, -2.5645) -> (-34, -47.5645)
  line L32 (-39, -47.5645) -> (-36.5, -47.5645)
  line L33 (-39, -2.5645) -> (-39, -47.5645)
  line L34 (-36.5, -2.5645) -> (-39, -2.5645)
  line L35 (-36.5, -47.5645) -> (-36.5, -2.5645)
  line L36 (-69, -47.5645) -> (-71.5, -47.5645)
  line L37 (-69, -2.5645) -> (-69, -47.5645)
  line L38 (-71.5, -2.5645) -> (-69, -2.5645)
  line L39 (-71.5, -47.5645) -> (-71.5, -2.5645)
  line L40 (-54, -2.5645) -> (-54, -52.5645)
  line L41 (-101.5356, 31) -> (-101.5356, -82.5645)
  line L42 (-101.5356, 126.1027) -> (-101.5356, 31)
  circle C1 centre (-54, -52.5645) radius 1
  circle C2 centre (-54, -71.4746) radius 1
  circle C3 centre (-54, -64) radius 1
  circle C4 centre (-101.5356, -50.4038) radius 1
  circle C5 centre (-101.5356, -9.2833) radius 1
  circle C6 centre (-101.5356, 31) radius 1
  circle C7 centre (-101.5356, 117.6424) radius 1
  circle C8 centre (-101.5356, 78.3036) radius 1
  point P14 (-109.3548, -82.5645)
  point P13 (-77.3814, 126.1027)
  point P16 (-77.3814, 126.1027)
  point P20 (-54, -82.5645)
  point P26 (-54, -52.5645)
  point P21 (-54, -52.5645)
  point P39 (-54, -52.5645)
  point P40 (-54, -2.5645)
  point P41 (-54, -52.5645)
  point P42 (-54, -71.4746)
  point P43 (-54, -64)
  point P44 (-101.5356, -82.5645)
  point P45 (-101.5356, -50.4038)
  point P46 (-101.5356, -9.2833)
  point P47 (-101.5356, 31)
  point P48 (-101.5356, 31)
  point P49 (-101.5356, 126.1027)
  point P50 (-101.5356, 117.6424)
  point P51 (-101.5356, 78.3036)
  point P15 (-109.3548, -52.5645)
  point P17 (-97.3814, 126.1027)
  point P24 (-74, -102.5645)
  point P25 (-34, -102.5645)
  point P23 (-74, -2.5645)
  point P27 (-71.5, -2.5645)
  point P29 (-74, -47.5645)
  point P22 (-34, -2.5645)
  point P30 (-36.5, -2.5645)
  point P31 (-36.5, -47.5645)
  point P33 (-39, -47.5645)
  point P28 (-71.5, -47.5645)
  point P36 (-69, -47.5645)
  point P18 (-97.3814, -63.8973)
  coincident L2 P14
  perpendicular L2 L12
  horizontal L13
  vertical L14
  horizontal L15
  vertical L16
  coincident P13 P16
  midpoint L2 P20
  perpendicular L2 L17
  horizontal L18
  perpendicular L18 L19
  parallel L18 L20
  parallel L19 L21
  coincident L22 P26
  coincident L23 P26
  coincident P21 P26
  horizontal L24
  vertical L25
  horizontal L26
  vertical L27
  vertical L29
  perpendicular L28 L29
  horizontal L30
  vertical L31
  vertical L33
  perpendicular L32 L33
  horizontal L34
  vertical L35
  vertical L37
  perpendicular L36 L37
  horizontal L38
  vertical L39
  coincident P26 P39
  midpoint L18 P40
  coincident P39 P41
  coincident L17 P42
  coincident L17 P43
  coincident L2 P44
  perpendicular L2 L41
  coincident L41 P45
  coincident L41 P46
  coincident L41 P47
  coincident P47 P48
  coincident P47 P48
  coincident L8 P49
  perpendicular L8 L42
  coincident L42 P50
  coincident L42 P51
  dimension "d1201" distance P14 P15 = 30
  dimension "d1202" distance P16 P17 = 20
  dimension "d1203" distance P20 P21 = 30
  dimension "d1204" distance P24 P25 = 40
  dimension "d1205" distance P23 P24 = 100
  dimension "d1206" distance P23 P27 = 2.5
  dimension "d1207" distance P23 P29 = 45
  dimension "d1208" distance P22 P30 = 2.5
  dimension "d1209" distance P31 P33 = 2.5
  dimension "d1210" distance P28 P36 = 2.5
  dimension "d1218" distance P17 P18 = 190
  dimension "d1223" diameter C1 = 2
  dimension "d1224" diameter C2 = 2
  dimension "d1225" diameter C3 = 2
  dimension "d1226" diameter C4 = 2
  dimension "d1227" diameter C5 = 2
  dimension "d1228" diameter C6 = 2
  dimension "d1229" diameter C7 = 2
  dimension "d1230" diameter C8 = 2
extrude "Extrude75" cut sketch "Sketch32" profile of L11 L13 L14 L15 L16 against normal blind 5
extrude "Extrude76" add sketch "Sketch32" profile of L18 L19 L21 L24 L25 L26 L27 L28 L29 L30 L31 L35 L39 along normal blind 5
extrude "Extrude77" add sketch "Sketch32" profile of L18 L25 L29 L32 L33 L34 L35 L36 L37 L38 L39 blind 2 from offset 3
offset_faces "OffsetFaces3" distance -3
offset_faces "OffsetFaces4" distance -3
fillet "Fillet11" radius 2
extrude "Extrude78" cut sketch "Sketch32" profile of C1 C2 C3 C4 C5 C6 C7 C8 against normal blind 4
offset_faces "OffsetFaces1" distance -0.4
sketch "Sketch4" plane through (126, 0, 0) normal (-1, 0, 0) x axis (0, -1, 0)
  curve K1 (18.4358, 58.2989) -> (0, 95.1438)
  curve K2 (0, 95.1438) -> (-18.4358, 58.2989)
  arc A1 centre (0, 70.6) radius 22.1629 clockwise from (18.4358, 58.2989) to (-18.4358, 58.2989)
  circle C1 centre (0, 70.6) radius 4.1
  circle C2 centre (0, 70.6) radius 11.1
  concentric A1 C2
  dimension "d1234" diameter C2 = 22.2
extrude "Extrude8" cut sketch "Sketch4" profile of C1 C2 against normal blind 7
component_from_bodies "Body->Comp1"
component_from_bodies "Body->Comp2"
component_from_bodies "Body->Comp3"
component_from_bodies "Body->Comp4"
sketch "Sketch5" plane through (135.8025, 0, 0) normal (1, 0, 0) x axis (0, 1, 0)
  curve K1 (-42.0969, 92.8551) -> (-42.4569, 81.9281)
  curve K2 (-35.7603, 81.9281) -> (-36.1203, 92.8551)
  curve K3 (-42.0969, 202.8551) -> (-42.4569, 191.9281)
  curve K4 (-35.7603, 191.9281) -> (-36.1203, 202.8551)
  line L1 (52.3693, 255.1758) -> (52.3693, 30.245)
  line L2 (1.9988, 255.1758) -> (52.3693, 255.1758)
  line L3 (-36.0257, 253.4503) -> (-3.2602, 255.1758)
  curve K5 (-36.0257, 253.4503) -> (-39.9781, 236.096)
  line L4 (32.3693, 30.245) -> (2.1894, 30.245)
  line L5 (52.3693, 30.245) -> (32.3693, 30.245)
  line L6 (-10.6307, 119.245) -> (32.3693, 119.245)
  line L7 (-18.6307, 145.245) -> (-18.6307, 127.245)
  line L8 (32.3693, 153.245) -> (-10.6307, 153.245)
  line L9 (40.3693, 127.245) -> (40.3693, 145.245)
  curve K6 (3.3853, 45.9804) -> (18.082, 84.0954)
  curve K7 (-6.8655, 92.093) -> (-17.0683, 52.5374)
  line L10 (-25, 220.4) -> (-25, 190.4)
  line L11 (15, 230.4) -> (-15, 230.4)
  line L12 (25, 190.4) -> (25, 220.4)
  line L13 (-15, 180.4) -> (15, 180.4)
  line L14 (-36.0257, 253.4503) -> (52.3693, 253.4503)
  curve K8 (-36.0257, 253.4503) -> (-39.9781, 236.096)
  line L15 (32.3693, 30.245) -> (2.1894, 30.245)
  line L16 (52.3693, 30.245) -> (32.3693, 30.245)
  line L17 (52.3693, 253.4503) -> (52.3693, 30.245)
  line L18 (34.3693, 213.245) -> (34.3693, 194.245)
  line L19 (41.3693, 213.245) -> (34.3693, 213.245)
  line L20 (41.3693, 194.245) -> (41.3693, 213.245)
  line L21 (34.3693, 194.245) -> (41.3693, 194.245)
  line L22 (-36.2739, 253.4503) -> (52.3693, 253.4503)
  line L23 (-36.2739, 259.7274) -> (-36.2739, 253.4503)
  line L24 (52.3693, 259.7274) -> (-36.2739, 259.7274)
  line L25 (52.3693, 253.4503) -> (52.3693, 259.7274)
  arc A1 centre (-39.1086, 86.6236) radius 6.911 clockwise from (-42.0969, 92.8551) to (-36.1203, 92.8551)
  arc A2 centre (-39.1086, 86.6236) radius 5.767 clockwise from (-35.7603, 81.9281) to (-42.4569, 81.9281)
  arc A3 centre (-39.1086, 196.6236) radius 6.911 clockwise from (-42.0969, 202.8551) to (-36.1203, 202.8551)
  arc A4 centre (-39.1086, 196.6236) radius 5.767 clockwise from (-35.7603, 191.9281) to (-42.4569, 191.9281)
  circle C1 centre (27.5, 205.4) radius 1.65
  circle C2 centre (0, 177.9) radius 1.65
  circle C3 centre (-27.5, 205.4) radius 1.65
  circle C4 centre (0, 232.9) radius 1.65
  arc A5 centre (-0.6307, 205.245) radius 50 clockwise from (-3.2602, 255.1758) to (1.9988, 255.1758)
  arc A6 centre (-0.6307, 205.245) radius 50 clockwise from (-41.2627, 176.1067) to (-39.9781, 236.096)
  arc A7 centre (-81.8947, 146.9684) radius 50 clockwise from (-41.2627, 176.1067) to (-32.4457, 139.5658)
  arc A8 centre (-2.3992, 135.0677) radius 30.3814 clockwise from (-32.7706, 134.2915) to (-32.4457, 139.5658)
  arc A9 centre (-82.7543, 133.0139) radius 50 clockwise from (-32.7706, 134.2915) to (-40.2825, 106.6295)
  arc A10 centre (2.1894, 80.245) radius 50 clockwise from (2.1894, 30.245) to (-40.2825, 106.6295)
  arc A11 centre (32.3693, 127.245) radius 8 clockwise from (40.3693, 127.245) to (32.3693, 119.245)
  arc A12 centre (-10.6307, 127.245) radius 8 clockwise from (-10.6307, 119.245) to (-18.6307, 127.245)
  arc A13 centre (-10.6307, 145.245) radius 8 clockwise from (-18.6307, 145.245) to (-10.6307, 153.245)
  arc A14 centre (32.3693, 145.245) radius 8 clockwise from (32.3693, 153.245) to (40.3693, 145.245)
  circle C5 centre (39.3288, 119.0404) radius 1.4
  circle C6 centre (39.3288, 153.4496) radius 1.4
  circle C7 centre (-17.5719, 118.2036) radius 1.4
  circle C8 centre (-18.5837, 152.598) radius 1.4
  arc A15 centre (0, 70.6) radius 24.8512 clockwise from (3.3853, 45.9804) to (-17.0683, 52.5374)
  arc A16 centre (0, 70.6) radius 22.5629 clockwise from (-6.8655, 92.093) to (18.082, 84.0954)
  arc A17 centre (-15, 220.4) radius 10 clockwise from (-25, 220.4) to (-15, 230.4)
  arc A18 centre (15, 220.4) radius 10 clockwise from (15, 230.4) to (25, 220.4)
  arc A19 centre (15, 190.4) radius 10 clockwise from (25, 190.4) to (15, 180.4)
  arc A20 centre (-15, 190.4) radius 10 clockwise from (-15, 180.4) to (-25, 190.4)
  arc A21 centre (-0.6307, 205.245) radius 50 clockwise from (-41.2627, 176.1067) to (-39.9781, 236.096)
  arc A22 centre (-81.8947, 146.9684) radius 50 clockwise from (-41.2627, 176.1067) to (-32.4457, 139.5658)
  arc A23 centre (-2.3992, 135.0677) radius 30.3814 clockwise from (-32.7706, 134.2915) to (-32.4457, 139.5658)
  arc A24 centre (-82.7543, 133.0139) radius 50 clockwise from (-32.7706, 134.2915) to (-40.2825, 106.6295)
  arc A25 centre (2.1894, 80.245) radius 50 clockwise from (2.1894, 30.245) to (-40.2825, 106.6295)
  circle C9 centre (-39.1086, 86.6236) radius 7
  circle C10 centre (-39.1086, 196.6236) radius 7
  point P66 (52.3693, 253.4503)
  point P87 (52.3693, 253.4503)
  horizontal L22
  vertical L23
  horizontal L24
  vertical L25
  coincident P66 P87
extrude "Extrude1" cut sketch "Sketch5" profile of L1 L2 A5 L3 L14 L22 L25 against normal blind 7
sketch "Sketch1" plane through (-17, 0, 0) normal (1, 0, 0) x axis (0, 1, 0)
  line L1 (-35.395, 253.2053) -> (53, 253.2053)
  curve K1 (-35.395, 253.2053) -> (-39.3474, 235.851)
  line L2 (33, 30) -> (2.8201, 30)
  line L3 (53, 30) -> (33, 30)
  line L4 (53, 253.2053) -> (53, 30)
  line L5 (35, 213) -> (35, 194)
  line L6 (42, 213) -> (35, 213)
  line L7 (42, 194) -> (42, 213)
  line L8 (35, 194) -> (42, 194)
  arc A1 centre (0, 205) radius 50 clockwise from (-40.632, 175.8617) to (-39.3474, 235.851)
  arc A2 centre (-81.264, 146.7234) radius 50 clockwise from (-40.632, 175.8617) to (-31.815, 139.3208)
  arc A3 centre (-1.7685, 134.8228) radius 30.3814 clockwise from (-32.1399, 134.0465) to (-31.815, 139.3208)
  arc A4 centre (-82.1236, 132.769) radius 50 clockwise from (-32.1399, 134.0465) to (-39.6517, 106.3845)
  arc A5 centre (2.8201, 80) radius 50 clockwise from (2.8201, 30) to (-39.6517, 106.3845)
  circle C1 centre (-38.4779, 86.3786) radius 7
  circle C2 centre (-38.4779, 196.3786) radius 7
  circle C3 centre (-38.4779, 196.3786) radius 5.1
  circle C4 centre (-38.4779, 86.3786) radius 5.1
  concentric C2 C3
  concentric C1 C4
  dimension "d1254" diameter C3 = 10.2
  dimension "d1255" diameter C4 = 10.2
extrude "Extrude1" add sketch "Sketch1" profile of C1 C2 C3 C4 against normal blind 4
combine "Combine1"
offset_faces "OffsetFaces1" distance -3
combine "Combine1"
combine "Combine2"
combine "Combine3"
combine "Combine4"
combine "Combine1"
offset_faces "OffsetFaces1" distance 3
offset_faces "OffsetFaces2" distance 1.5
combine "Combine2"
position "Position30"
extrude "Extrude2" add of existing geometry blind 1.772
offset_faces "OffsetFaces1" distance 2
position "Position31"
extrude "Extrude3" add of existing geometry to an object
sketch "Sketch2" plane through (-18, 0, 0) normal (-1, 0, 0) x axis (0, -1, 0)
  line L1 (-18.6307, 104.755) -> (-46.1387, 104.755)
  line L2 (-15.6307, 175.7967) -> (-15.6307, 107.755)
  line L3 (-46.1387, 178.7967) -> (-18.6307, 178.7967)
  line L4 (-49.1387, 107.755) -> (-49.1387, 175.7967)
  line L5 (-22.6991, 109.9347) -> (-41.618, 109.9347)
  line L6 (-22.6991, 106.722) -> (-22.6991, 109.9347)
  line L7 (-41.618, 106.722) -> (-22.6991, 106.722)
  line L8 (-41.618, 109.9347) -> (-41.618, 106.722)
  arc A1 centre (-46.1387, 107.755) radius 3 clockwise from (-46.1387, 104.755) to (-49.1387, 107.755)
  arc A2 centre (-18.6307, 107.755) radius 3 clockwise from (-15.6307, 107.755) to (-18.6307, 104.755)
  arc A3 centre (-18.6307, 175.7967) radius 3 clockwise from (-18.6307, 178.7967) to (-15.6307, 175.7967)
  arc A4 centre (-46.1387, 175.7967) radius 3 clockwise from (-49.1387, 175.7967) to (-46.1387, 178.7967)
  horizontal L5
  vertical L6
  horizontal L7
  vertical L8
extrude "Extrude4" cut sketch "Sketch2" profile of L5 L6 L7 L8 to an object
